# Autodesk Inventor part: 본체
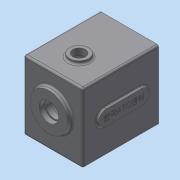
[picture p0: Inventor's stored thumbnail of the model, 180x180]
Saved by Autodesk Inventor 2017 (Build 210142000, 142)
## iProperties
Created: 2016-02
Part Number: 본체
Material: 알루미늄 6061
Document SubType Name: Modeling
Designer: mduedu
Density: 2.7 g/cm^3
Mass: 1511.55 g
Surface Area: 1073.15 cm^2
Volume: 559.832 cm^3
Appearance: 기본값
Author: mduedu
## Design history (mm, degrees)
sketch "스케치1"
  geometry: L1 (-47, -47)-(47, -47); L2 (47, -47)-(47, 63); L3 (47, 63)-(-47, 63); L4 (-47, 63)-(-47, -47); 2 further points
  constraints: 8 end point, 2 parallel, 1 horizontal, 1 midpoint, 1 perpendicular, 1 vertical alignment
  dimensions: "d0" = 94 distance of L2.end L3.end; "d155" = 110 distance of L1.end L2.end; "d156" = 47 distance from line of L1 point (0, 0)
extrude "돌출1" new body sketch "스케치1" distance "d2" = 120; taper "d3" = 0 deg
sketch "스케치3"
  geometry: L1 (47, -47)-(-47, -47) reference; L2 (47, 63)-(47, -47) reference; L3 (-47, 63)-(47, 63) reference; L4 (-47, -47)-(-47, 63) reference; L5 (37, 53)-(37, -37); L6 (37, -37)-(-37, -37); L7 (-37, -37)-(-37, 53); L8 (-37, 53)-(37, 53); 1 further point
  constraints: 8 end point, 3 other
  dimensions: "d226" = 10 distance between parallel lines of L8 L3
extrude "돌출3" cut sketch "스케치3" distance "d11" = 110; taper "d12" = 0 deg
sketch "스케치4"
  geometry: C1 r 21 at (0, 11); 1 further point
  constraints: 1 centre point, 1 vertical alignment
  dimensions: "d13" = 21 radius of C1; "d227" = 11 distance of point (0, 0) C1.centre
extrude "돌출4" join sketch "스케치4" distance "d16" = 7; taper "d17" = 0 deg
sketch "스케치5"
  geometry: C1 r 15 at (0, -20); 1 further point
  constraints: 1 centre point, 1 vertical alignment
  dimensions: "d18" = 15 radius of C1; "d20" = 20 distance of point (0, 0) C1.centre
extrude "돌출5" join sketch "스케치5" distance "d21" = 7; taper "d22" = 0 deg
sketch "스케치6"
  geometry: C1 r 30 at (0, 11); A1 r 21 centre (0, 11) between (8.978, -7.984) and (-8.978, -7.984) reference; 1 further point
  constraints: 1 centre point, 1 coincident
  dimensions: "d228" = 60 diameter of C1
extrude "돌출6" join sketch "스케치6" distance "d25" = 7; taper "d26" = -3 deg
hole "구멍1" diameter "d29" = 30; stored, may be unused: countersink angle "d33" = 90 deg, drill point angle "d35" = 0 deg; dims "d30" = 6, "d31" = 4, "d32" = 2, "d34" = 7, "d269" = 10, "d270" = 10
hole "구멍2" diameter "d38" = 22; stored, may be unused: countersink angle "d42" = 90 deg, drill point angle "d44" = 0 deg; dims "d36" = 10, "d37" = 10, "d39" = 6, "d40" = 4, "d41" = 2, "d43" = 7
hole "구멍3" diameter "d47" = 19; stored, may be unused: countersink angle "d51" = 90 deg, drill point angle "d53" = 0 deg; dims "d45" = 10, "d46" = 10, "d48" = 6, "d49" = 4, "d50" = 2, "d52" = 1
hole "구멍4" diameter "d56" = 30; stored, may be unused: countersink angle "d60" = 90 deg, drill point angle "d62" = 0 deg; dims "d57" = 6, "d58" = 4, "d59" = 2, "d61" = 8.3, "d271" = 10, "d272" = 10
hole "구멍5" diameter "d65" = 26; stored, may be unused: countersink angle "d69" = 90 deg, drill point angle "d71" = 0 deg; dims "d66" = 6, "d67" = 4, "d68" = 2, "d70" = 8, "d267" = 10, "d268" = 10
fillet "모깎기2" dims "d73" = 0.3
fillet "모깎기3" dims "d74" = 2
chamfer "모따기1" distance "d75" = 1; stored, may be unused: second distance "d76" = 2, angle "d77" = 45 deg
fillet "모깎기4" dims "d78" = 3
fillet "모깎기23" dims "d240" = 1
fillet "모깎기20" dims "d229" = 3
sketch "스케치23"
  geometry: L1 (-37, 53)-(37, 53) reference; L2 (37, 53)-(37, -37) reference; L3 (37, -37)-(-37, -37) reference; L4 (-37, -37)-(-37, 53) reference; L5 (44, -47)-(-44, -47) reference; L6 (47, 60)-(47, -44) reference; L7 (-44, 63)-(44, 63) reference; L8 (-47, -44)-(-47, 60) reference; C1 r 10 at (-37, 53); C2 r 10 at (37, 53); C3 r 10 at (-37, -37); C4 r 10 at (37, -37); A1 r 3 centre (-44, -44) between (-47, -44) and (-44, -47) reference; A2 r 3 centre (44, -44) between (44, -47) and (47, -44) reference; A3 r 3 centre (44, 60) between (47, 60) and (44, 63) reference; A4 r 3 centre (-44, 60) between (-44, 63) and (-47, 60) reference; 1 further point
  constraints: 4 centre point, 4 coincident, 3 equal radius
  dimensions: "d230" = 20 diameter of C1
extrude "돌출22" join sketch "스케치23" stored distance "d235" = 10; taper "d236" = 0 deg
fillet "모깎기21" dims "d237" = 3
node "작업 평면1"
fillet "모깎기22" dims "d239" = 1
sketch "스케치12"
  geometry: A1 r 10 centre (-37, 53) between (-34.692, 43.27) and (-27.27, 50.692) reference; A2 r 10 centre (37, 53) between (27.27, 50.692) and (34.692, 43.27) reference; A3 r 10 centre (37, -37) between (34.692, -27.27) and (27.27, -34.692) reference; A4 r 10 centre (-37, -37) between (-27.27, -34.692) and (-34.692, -27.27) reference; 5 further points
  constraints: 4 coincident
hole "구멍6" sketch "스케치12" at (-37, 53), (37, 53), (37, -37), (-37, -37) diameter "d122" = 3.242; stored, may be unused: countersink angle "d126" = 90 deg, drill point angle "d128" = 120 deg; dims "d123" = 7, "d124" = 4, "d125" = 2, "d127" = 9
sketch "스케치20"
  geometry: L1 (44, 0)-(-44, 0) reference; L2 (44, -120)-(-44, -120) reference; L3 (0, 0)-(0, -120); L4 (-44, -120)-(-44, 0) reference; L5 (44, 0)-(44, -120) reference; C1 r 10 at (0, -79)
  constraints: 2 end point, 1 centre point, 1 midpoint, 1 point on line
  dimensions: "d189" = 20 diameter of C1; "d190" = 41 distance from line of C1.centre L2
extrude "돌출19" cut sketch "스케치20" stored distance "d191" = 10; taper "d192" = 0 deg
sketch "스케치18"
  geometry: C1 r 15 at (0, -79); C2 r 10 at (0, -79) reference; 1 further point
  constraints: 1 centre point, 1 concentric
  dimensions: "d174" = 30 diameter of C1
extrude "돌출17" join sketch "스케치18" distance "d175" = 5; taper "d176" = 0 deg
fillet "모깎기16" dims "d177" = 3
sketch "스케치19"
  geometry: C1 r 15 at (24.351, 79); C2 r 10 at (24.351, 79) reference; 1 further point
  constraints: 1 centre point, 1 concentric
  dimensions: "d178" = 30 diameter of C1
extrude "돌출18" cut sketch "스케치19" distance "d181" = 5; taper "d182" = 0 deg
chamfer "모따기5" distance "d183" = 1; stored, may be unused: second distance "d184" = 2, angle "d185" = 45 deg
fillet "모깎기24" dims "d242" = 3, "d243" = 3
sketch "스케치24"
  geometry: L1 (-86, 64)-(-30, 64); L2 (-30, 64)-(-30, 40); L3 (-30, 40)-(-86, 40); L4 (-86, 40)-(-86, 64); L5 (0, 0)-(0, 104) reference; L6 (-86, 52)-(-30, 52); L7 (-58, 64)-(-58, 40); A1 r 12 centre (-86, 52) between (-86, 40) and (-86, 64); A2 r 12 centre (-30, 52) between (-30, 64) and (-30, 40); A3 r 12 centre (-30, 52) between (-30, 40) and (-30, 64); A4 r 12 centre (-86, 52) between (-86, 64) and (-86, 40); 2 further points
  constraints: 12 end point, 8 point on circle, 5 midpoint, 4 centre point, 2 parallel, 2 perpendicular, 1 horizontal, 1 horizontal alignment
  dimensions: "d244" = 58 distance between parallel lines of L7 L5; "d245" = 80 dimension on A2 A1; "d246" = 24 distance between parallel lines of L3 L1
extrude "돌출23" join sketch "스케치24" distance "d247" = 3; taper "d248" = 0 deg
fillet "모깎기25" dims "d249" = 3
sketch "스케치25"
  geometry: L1 (-30, 64)-(-86, 64) reference; L2 (-86, 40)-(-30, 40) reference; A1 r 12 centre (-86, 52) between (-86, 64) and (-86, 40) reference; A2 r 12 centre (-30, 52) between (-30, 40) and (-30, 64) reference; 3 further points
  constraints: 1 horizontal alignment, 1 midpoint, 1 vertical alignment, 1 other
feature "엠보싱3" sketch "스케치25" dims "d32" = 2, "d250" = 0.5, "d251" = 0
sketch "스케치26"
  geometry: L1 (14.367, 127)-(73.633, 127) reference; L2 (0, 0)-(88, 0) reference; L3 (88, 120)-(0, 120) reference; 5 further points
  constraints: 3 vertical alignment, 2 midpoint
  dimensions: "d252" = 35 distance from line of point (44, 35) L2; "d253" = 35 distance from line of point (44, 85) L3; "d254" = 50 distance of point (44, 35) point (44, 85) (derived)
hole "구멍8" sketch "스케치26" at (44, 85), (44, 35) diameter "d255" = 6.647; stored, may be unused: countersink angle "d259" = 90 deg, drill point angle "d261" = 118 deg; dims "d256" = 6, "d257" = 4, "d258" = 2, "d260" = 8
chamfer "모따기7" distance "d262" = 0.8; stored, may be unused: second distance "d263" = 2, angle "d264" = 30 deg
node "솔리드1"
node "투영된 루프1"
node "투영된 루프4"
node "투영된 루프5"
node "투영된 루프6"
